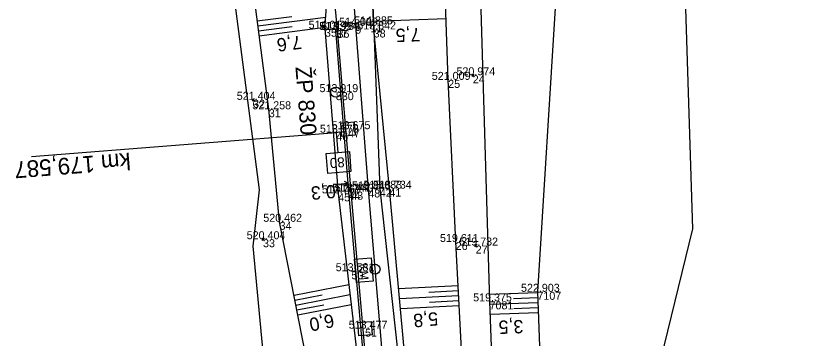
# Model space of a CAD drawing. Extents: x -1234191 to 23050, y -1290331 to -741191.
# Drawn here: x -865468.6 to -865348.1, y -1105473 to -1105424.6 of the extents above; entities that cross this region are included whole.
import ezdxf

# ---------------------------------------------------------------- set-up
doc = ezdxf.new("R2010")
doc.units = 0
for name, color, linetype in [('Vrstva 1', 7, 'Continuous'), ('Vrstva 13', 7, 'Continuous'), ('Vrstva 4', 7, 'Continuous'), ('Vrstva 41', 7, 'Continuous'), ('Vrstva 48', 7, 'Continuous'), ('Vrstva 49', 7, 'Continuous'), ('Vrstva 5', 7, 'Continuous'), ('Vrstva 53', 7, 'Continuous'), ('Vrstva 60', 7, 'Continuous'), ('Vrstva 61', 7, 'Continuous'), ('Vrstva 63', 7, 'Continuous'), ('Vrstva 7', 7, 'Continuous')]:
    doc.layers.add(name, color=color, linetype=linetype)

msp = doc.modelspace()

# ---------------------------------------------------------------- linework, layer by layer
at = {"layer": 'Vrstva 1'}
msp.add_lwpolyline([(-865418.83, -1105411.43), (-865417.75, -1105426.01), (-865415.82, -1105450.59), (-865413.78, -1105474.89), (-865411.86, -1105496.43), (-865409.62, -1105518.22), (-865407.2, -1105537.57), (-865404.2, -1105556.92)], dxfattribs=at)
at = {"layer": 'Vrstva 13'}
msp.add_line((-865420.87, -1105449.82), (-865418.87, -1105449.66), dxfattribs=at)
for points in [[(-865420.43, -1105426.62), (-865420.71, -1105426.65), (-865418.77, -1105450.92), (-865416.65, -1105475.09), (-865414.73, -1105496.67), (-865412.6, -1105518.49), (-865410.27, -1105538.13), (-865407.28, -1105557.54)], [(-865406.87, -1105557.41), (-865409.86, -1105538.2), (-865412.23, -1105518.23), (-865414.32, -1105496.69), (-865416.28, -1105475.04), (-865418.37, -1105450.92), (-865420.43, -1105426.62)], [(-865419.35, -1105450), (-865418.87, -1105449.66), (-865419.39, -1105449.4)]]:
    msp.add_lwpolyline(points, dxfattribs=at)
at = {"layer": 'Vrstva 4'}
for points in [[(-865415.79, -1105407.51), (-865415.01, -1105426.56), (-865414.09, -1105450.47), (-865411.46, -1105474.69), (-865410.07, -1105496.27), (-865407.86, -1105518.06), (-865405.51, -1105537.28), (-865402.3, -1105556.57), (-865398.44, -1105575.52), (-865393.92, -1105595.1), (-865389.46, -1105614.69), (-865383.95, -1105633.21), (-865377.69, -1105651.78), (-865370.49, -1105670.43), (-865362.74, -1105688.31), (-865354.73, -1105705.92), (-865346.08, -1105723.23), (-865337.3, -1105740.11), (-865328.12, -1105756.48), (-865310.18, -1105788.44), (-865292.19, -1105820.36)], [(-865241.39, -1105918.85), (-865246.2, -1105909.18), (-865270.79, -1105865.58), (-865295.11, -1105821.95), (-865312.96, -1105790.18), (-865331.02, -1105758.11), (-865339.94, -1105741.48), (-865348.82, -1105724.71), (-865357.64, -1105707.33), (-865365.7, -1105689.59), (-865373.31, -1105671.54), (-865380.29, -1105652.6), (-865386.74, -1105634.02), (-865392.22, -1105615.41), (-865397.53, -1105595.97), (-865401.98, -1105576.34), (-865405.63, -1105557.2), (-865408.67, -1105537.76), (-865411.14, -1105518.31), (-865413.54, -1105496.5), (-865416.28, -1105475.04), (-865418.37, -1105450.92), (-865420.43, -1105426.62), (-865421.34, -1105417.32)]]:
    msp.add_lwpolyline(points, dxfattribs=at)
at = {"layer": 'Vrstva 41'}
for points in [[(-865417.92, -1105440.46), (-865417.76, -1105442.46), (-865419.76, -1105442.62), (-865419.91, -1105440.62), (-865417.92, -1105440.46)], [(-865415.39, -1105470.4), (-865415.22, -1105472.4), (-865417.22, -1105472.57), (-865417.38, -1105470.57), (-865415.39, -1105470.4)]]:
    msp.add_lwpolyline(points, dxfattribs=at)
at = {"layer": 'Vrstva 48'}
for p, q in [((-865432.45, -1105425.27), (-865427.29, -1105424.6)), ((-865432.35, -1105426.02), (-865422.18, -1105424.7)), ((-865404.17, -1105424.98), (-865415.06, -1105425.37)), ((-865432.26, -1105426.76), (-865427.25, -1105426.11)), ((-865432.16, -1105427.51), (-865422.3, -1105426.23)), ((-865426.95, -1105466.46), (-865418.74, -1105464.86)), ((-865402.36, -1105465.05), (-865411.28, -1105465.53)), ((-865402.32, -1105465.8), (-865406.76, -1105466.04)), ((-865426.81, -1105467.2), (-865422.73, -1105466.4)), ((-865426.67, -1105467.94), (-865418.56, -1105466.35)), ((-865402.28, -1105466.55), (-865411.14, -1105467.03)), ((-865390.47, -1105466.11), (-865397.67, -1105466.38)), ((-865390.44, -1105466.86), (-865394.05, -1105466.99)), ((-865426.52, -1105468.67), (-865422.5, -1105467.89)), ((-865426.38, -1105469.41), (-865418.39, -1105467.85)), ((-865402.2, -1105468.05), (-865411, -1105468.52)), ((-865402.24, -1105467.3), (-865406.65, -1105467.54)), ((-865390.41, -1105467.61), (-865397.62, -1105467.88)), ((-865390.36, -1105469.11), (-865397.57, -1105469.37)), ((-865390.39, -1105468.36), (-865393.99, -1105468.49))]:
    msp.add_line(p, q, dxfattribs=at)
at = {"layer": 'Vrstva 49'}
for p, q in [((-865400.34, -1105433.29), (-865399.96, -1105433.62)), ((-865399.99, -1105433.26), (-865400.31, -1105433.64)), ((-865433.27, -1105436.97), (-865432.89, -1105437.29)), ((-865432.92, -1105436.94), (-865433.24, -1105437.32)), ((-865431.78, -1105457.9), (-865431.4, -1105458.22)), ((-865431.42, -1105457.87), (-865431.75, -1105458.25)), ((-865399.91, -1105458.85), (-865399.53, -1105459.18)), ((-865399.56, -1105458.82), (-865399.88, -1105459.2))]:
    msp.add_line(p, q, dxfattribs=at)
for points in [[(-865376.08, -1105650.96), (-865382.42, -1105632.94), (-865388.77, -1105611.85), (-865393.22, -1105594.87), (-865397.35, -1105575.35), (-865401.05, -1105556.12), (-865404.23, -1105536.89), (-865406.54, -1105517.77), (-865408.64, -1105496.06), (-865410.44, -1105474.57), (-865412.66, -1105450.47), (-865415.01, -1105426.56), (-865415.79, -1105407.51), (-865415.46, -1105367.24), (-865402.91, -1105366.08)], [(-865376.08, -1105650.96), (-865381.49, -1105628.02), (-865385.33, -1105613.53), (-865389.71, -1105593.56), (-865393.1, -1105574.33), (-865395.67, -1105556.25), (-865397.92, -1105536.92), (-865399.63, -1105517.59), (-865400.81, -1105494.21), (-865401.64, -1105478.42), (-865402.71, -1105458.47), (-865403.84, -1105434.14), (-865404.66, -1105411.01), (-865404.93, -1105394.99), (-865404.52, -1105373.59), (-865402.91, -1105366.08)], [(-865422.31, -1105426.46), (-865421.56, -1105416.49), (-865428.34, -1105417.13), (-865429.2, -1105406.06), (-865423.57, -1105404.92), (-865426.56, -1105368.16), (-865439.83, -1105369.36)], [(-865351.97, -1105725.83), (-865369.94, -1105691.32), (-865377.16, -1105673.07), (-865384.45, -1105654.06), (-865390.82, -1105634.91), (-865396.67, -1105615.66), (-865402.69, -1105596.97), (-865408.37, -1105576.11), (-865412.45, -1105559.08), (-865416.15, -1105538.99), (-865419.73, -1105517.79), (-865422.38, -1105496.03), (-865425.12, -1105475.83), (-865429.11, -1105455.44), (-865430.73, -1105438.55), (-865434.48, -1105409.62)], [(-865399.15, -1105416.76), (-865397.64, -1105467.39), (-865396.34, -1105502.42), (-865392.84, -1105533.61), (-865389.24, -1105568.11), (-865386.17, -1105592.38)], [(-865387.69, -1105421.66), (-865390.47, -1105465.95), (-865389.12, -1105502.7), (-865386.88, -1105534.5), (-865385.21, -1105559.66), (-865379.83, -1105594.38)], [(-865422.31, -1105426.46), (-865420.33, -1105451.17), (-865417.49, -1105475.54), (-865415.59, -1105496.85), (-865413.09, -1105518.48), (-865410.27, -1105538.13), (-865407.28, -1105557.54), (-865403.54, -1105576.91), (-865399.27, -1105596.3), (-865393.93, -1105616.95), (-865388.24, -1105635.29), (-865382.22, -1105653.37), (-865374.74, -1105672.84), (-865366.66, -1105690.21), (-865358.53, -1105707.69), (-865354.5, -1105715.08), (-865354.89, -1105715.23), (-865355.57, -1105715.19), (-865351.97, -1105725.83)]]:
    msp.add_lwpolyline(points, dxfattribs=at)
at = {"layer": 'Vrstva 5'}
for p, q in [((-865466.29, -1105445.66), (-865420.62, -1105442.06)), ((-865419.88, -1105442), (-865421.37, -1105442.12)), ((-865420.62, -1105442.06), (-865420.39, -1105445.05))]:
    msp.add_line(p, q, dxfattribs=at)
msp.add_lwpolyline([(-865422.13, -1105445.19), (-865418.64, -1105444.91), (-865418.41, -1105447.9), (-865421.9, -1105448.18)], close=True, dxfattribs=at)
at = {"layer": 'Vrstva 53'}
for points in [[(-865401.73, -1105642.98), (-865417.63, -1105585.97), (-865424.49, -1105550.46), (-865433.05, -1105459.11), (-865432.13, -1105450.64), (-865436.38, -1105418.03), (-865442.37, -1105372.04), (-865443.53, -1105360.94), (-865451.45, -1105359.03), (-865457.01, -1105352.36), (-865460.16, -1105345.64), (-865461.75, -1105336.51), (-865458.39, -1105309.04), (-865454.41, -1105297.45), (-865462.17, -1105175.64), (-865449.11, -1105046.26), (-865448.86, -1105042.88)], [(-865368.27, -1105423.41), (-865367.22, -1105456.52), (-865375.2, -1105489.27), (-865369.7, -1105551.6), (-865370.63, -1105583.91), (-865368.46, -1105603.69), (-865326.5, -1105717.99), (-865321.81, -1105718.79), (-865313.84, -1105726.53), (-865332.54, -1105731.79), (-865234.42, -1105909.3), (-865227.66, -1105917.88)]]:
    msp.add_lwpolyline(points, dxfattribs=at)
at = {"layer": 'Vrstva 60'}
for p, q in [((-865417.75, -1105426.01), (-865417.75, -1105426.01)), ((-865415.49, -1105425.8), (-865415.49, -1105425.8)), ((-865422.31, -1105426.46), (-865422.31, -1105426.46)), ((-865420.71, -1105426.65), (-865420.71, -1105426.65)), ((-865420.43, -1105426.62), (-865420.43, -1105426.62)), ((-865415.01, -1105426.56), (-865415.01, -1105426.56)), ((-865403.84, -1105434.14), (-865403.84, -1105434.14)), ((-865400.15, -1105433.45), (-865400.15, -1105433.45)), ((-865420.68, -1105435.98), (-865420.68, -1105435.98)), ((-865433.08, -1105437.13), (-865433.08, -1105437.13)), ((-865430.73, -1105438.55), (-865430.73, -1105438.55)), ((-865418.84, -1105441.54), (-865418.84, -1105441.54)), ((-865420.62, -1105442.06), (-865420.62, -1105442.06)), ((-865420.33, -1105451.17), (-865420.33, -1105451.17)), ((-865418.77, -1105450.92), (-865418.77, -1105450.92)), ((-865418.37, -1105450.92), (-865418.37, -1105450.92)), ((-865415.82, -1105450.59), (-865415.82, -1105450.59)), ((-865414.09, -1105450.47), (-865414.09, -1105450.47)), ((-865412.66, -1105450.47), (-865412.66, -1105450.47)), ((-865429.11, -1105455.44), (-865429.11, -1105455.44)), ((-865431.59, -1105458.06), (-865431.59, -1105458.06)), ((-865402.71, -1105458.47), (-865402.71, -1105458.47)), ((-865399.72, -1105459.01), (-865399.72, -1105459.01)), ((-865418.34, -1105462.86), (-865418.34, -1105462.86)), ((-865390.47, -1105465.95), (-865390.47, -1105465.95)), ((-865397.64, -1105467.39), (-865397.64, -1105467.39)), ((-865416.3, -1105471.49), (-865416.3, -1105471.49))]:
    msp.add_line(p, q, dxfattribs=at)
at = {"layer": 'Vrstva 63'}
msp.add_line((-865420.68, -1105435.93), (-865420.67, -1105436.03), dxfattribs=at)
msp.add_circle((-865420.68, -1105435.98), 0.756, dxfattribs=at)
at = {"layer": 'Vrstva 7'}
for p, q in [((-865414.99, -1105425.76), (-865415.98, -1105425.84)), ((-865415.52, -1105425.3), (-865415.45, -1105426.3)), ((-865418.34, -1105462.86), (-865417.72, -1105462.81))]:
    msp.add_line(p, q, dxfattribs=at)
msp.add_lwpolyline([(-865417.87, -1105461.07), (-865415.39, -1105460.86), (-865415.1, -1105464.34), (-865417.58, -1105464.55)], close=True, dxfattribs=at)
msp.add_circle((-865414.81, -1105462.56), 0.75, dxfattribs=at)

# ---------------------------------------------------------------- texts
at = {"layer": 'Vrstva 13'}
msp.add_text('0,3', height=2, rotation=184.8409, dxfattribs=at).set_placement((-865420.78, -1105449.86))
at = {"layer": 'Vrstva 48'}
for s, rotation, p in [('7,5', 182.0254, (-865408.03, -1105426.34)), ('7,6', 187.3801, (-865425.94, -1105427.47)), ('6,0', 191.0487, (-865421.15, -1105469.25)), ('5,8', 185.2525, (-865405.45, -1105468.98)), ('3,5', 182.1069, (-865392.61, -1105470.16))]:
    msp.add_text(s, height=2, rotation=rotation, dxfattribs=at).set_placement(p)
at = {"layer": 'Vrstva 5'}
for s, height, p in [('km 179,587', 2.5, (-865451.53, -1105445.06)), ('80', 1.5, (-865419.42, -1105445.73))]:
    msp.add_text(s, height=height, rotation=184.5024, dxfattribs=at).set_placement(p)
at = {"layer": 'Vrstva 60'}
for s, p in [('9', (-865417.75, -1105427.21)), ('11', (-865415.49, -1105427)), ('35', (-865422.31, -1105427.66)), ('37', (-865420.71, -1105427.85)), ('36', (-865420.43, -1105427.82)), ('38', (-865415.01, -1105427.77)), ('25', (-865403.84, -1105435.34)), ('24', (-865400.15, -1105434.65)), ('830', (-865420.68, -1105437.18)), ('32', (-865433.08, -1105438.33)), ('31', (-865430.73, -1105439.75)), ('47', (-865418.84, -1105442.74)), ('46', (-865420.62, -1105443.26)), ('45', (-865420.33, -1105452.37)), ('44', (-865418.77, -1105452.12)), ('43', (-865418.37, -1105452.12)), ('48', (-865415.82, -1105451.79)), ('42', (-865414.09, -1105451.67)), ('41', (-865412.66, -1105451.67)), ('34', (-865429.11, -1105456.64)), ('33', (-865431.59, -1105459.26)), ('26', (-865402.71, -1105459.67)), ('27', (-865399.72, -1105460.21)), ('50', (-865418.34, -1105464.06)), ('7107', (-865390.47, -1105467.15)), ('7081', (-865397.64, -1105468.59)), ('51', (-865416.3, -1105472.69))]:
    msp.add_text(s, height=1.2, dxfattribs=at).set_placement(p)
at = {"layer": 'Vrstva 61'}
for s, p in [('514.009', (-865420.2, -1105426.01)), ('514.385', (-865417.94, -1105425.8)), ('514.014', (-865424.76, -1105426.46)), ('513.994', (-865423.16, -1105426.65)), ('513.784', (-865422.88, -1105426.62)), ('513.842', (-865417.46, -1105426.56)), ('521.009', (-865406.3, -1105434.14)), ('520.974', (-865402.6, -1105433.45)), ('513.919', (-865423.13, -1105435.98)), ('521.404', (-865435.53, -1105437.13)), ('521.258', (-865433.19, -1105438.55)), ('513.675', (-865421.3, -1105441.54)), ('513.970', (-865423.07, -1105442.06)), ('513.767', (-865422.78, -1105451.17)), ('513.747', (-865421.22, -1105450.92)), ('513.440', (-865420.82, -1105450.92)), ('513.845', (-865418.27, -1105450.59)), ('513.683', (-865416.55, -1105450.47)), ('513.734', (-865415.11, -1105450.47)), ('520.462', (-865431.55, -1105455.44)), ('520.404', (-865434.04, -1105458.06)), ('519.611', (-865405.07, -1105458.47)), ('519.732', (-865402.17, -1105459.01)), ('513.581', (-865420.7, -1105462.86)), ('522.903', (-865392.93, -1105465.95)), ('519.375', (-865400.1, -1105467.39)), ('513.477', (-865418.75, -1105471.49))]:
    msp.add_text(s, height=1.2, dxfattribs=at).set_placement(p)
at = {"layer": 'Vrstva 63'}
msp.add_text('ŽP 830', height=2.4, rotation=274.5024, dxfattribs=at).set_placement((-865426.74, -1105432.21))
at = {"layer": 'Vrstva 7'}
msp.add_text('KM', height=1.247, rotation=274.7917, dxfattribs=at).set_placement((-865417.19, -1105461.74))

doc.saveas('drawing.dxf')
